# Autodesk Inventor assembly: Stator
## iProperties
Shininess: 64.0
Length Units: 11269
Angle Units: 11279
Time Units: 11290
Mass Units: 11283
Length Display Precision: 3
Angle Display Precision: 2
Compacted: True
Created: 2003-05
Part Number: Stator
Document SubType Name: Assembly
Designer: Philippe
Density: 0.0
Volumn: 0.0
Area: 0.0
PropertySet Name: Model Information
Control State: 0
Master: False
Checked Out: False
Author: Philippe
